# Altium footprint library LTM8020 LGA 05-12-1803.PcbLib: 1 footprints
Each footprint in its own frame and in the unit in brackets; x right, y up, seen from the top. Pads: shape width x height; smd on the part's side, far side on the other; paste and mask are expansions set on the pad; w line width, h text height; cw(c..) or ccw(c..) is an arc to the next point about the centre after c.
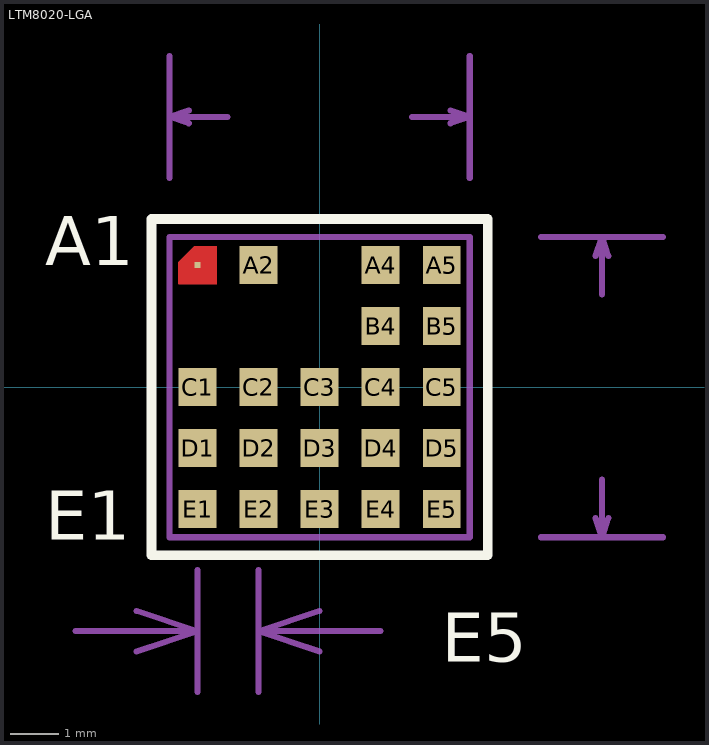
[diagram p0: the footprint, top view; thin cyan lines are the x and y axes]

## LTM8020-LGA [mil]
pads (21):
  rect 5x5 smd paste-3.5 mask-3: A1(-100,100)
  rect 31x31 smd paste-3.5 mask-3: A2(-50,100) A4(50,100) A5(100,100) B4(50,50) B5(100,50) C1(-100,0) C2(-50,0) C3(0,0) C4(50,0) C5(100,0) D1(-100,-50) D2(-50,-50) D3(0,-50) D4(50,-50) D5(100,-50) E1(-100,-100) E2(-50,-100) E3(0,-100) E4(50,-100) E5(100,-100)
TopLayer:
  region: -102.5,115.5 -84.5,115.5 -84.5,84.5 -115.5,84.5 -115.5,102.5
  lines w0.39: -115.5,84.5 -115.5,102.5 -102.5,115.5 -84.5,115.5 -84.5,84.5 -115.5,84.5
TopOverlay:
  lines w8: -137.8,-137.8 137.8,-137.8 137.8,137.8 -137.8,137.8 -137.8,-137.8
  text "E1" at -225,-125 h40
  text "A1" at -225,100 h40
  text "E5" at 100,-225 h40
Mechanical16:
  lines w5: -200,-200 -100,-200 ; -150,-216.67 -100,-200 ; -150,-183.33 -100,-200 ; -123.03,171.46 -123.03,271.46 ; -107.28,216.21 -123.03,221.46 ; -107.28,226.71 -123.03,221.46 ; -100,-250 -100,-150 ; -75.73,221.46 -123.03,221.46 ; -50,-250 -50,-150 ; 0,-216.67 -50,-200 ; 0,-183.33 -50,-200 ; 50,-200 -50,-200 ; 75.73,221.46 123.03,221.46 ; 107.28,216.21 123.03,221.46 ; 107.28,226.71 123.03,221.46 ; 123.03,171.46 123.03,271.46 ; 181.3,-123.03 281.3,-123.03 ; 181.3,123.03 281.3,123.03 ; 226.05,-107.28 231.3,-123.03 ; 226.05,107.28 231.3,123.03 ; 231.3,-75.73 231.3,-123.03 ; 231.3,75.73 231.3,123.03 ; 236.55,-107.28 231.3,-123.03 ; 236.55,107.28 231.3,123.03 ; -123.03,-123.03 123.03,-123.03 123.03,123.03 -123.03,123.03 -123.03,-123.03
  text "6.25 (mm)" at -65.73,210.83 h15.75
  text "6.25 (mm)" at 241.93,-65.73 h15.75
  text "1.27 (mm)" at -275.77,-319.97 h50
